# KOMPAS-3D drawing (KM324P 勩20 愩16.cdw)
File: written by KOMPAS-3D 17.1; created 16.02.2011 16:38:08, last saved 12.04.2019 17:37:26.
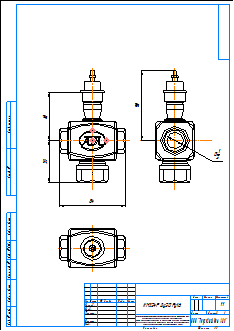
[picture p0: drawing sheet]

Title block, sheet 1: name: KM324P Ду20 Ру16; material: Внимание! Данный продукт является объектом авторского права ООО «Торговый Дом АДЛ». / Запрещается изменение, копирование, распространение / (в том числе путем копирования на другие сайты и ресурсы в Интернете) / или любое иное использование информации и объектов без предварительного / согласия правообладателя (ООО «Торговый Дом АДЛ»).; scale: 1:1; sheets: 1; organisation: ООО "Торговый дом АДЛ"; sheet format: A3; stored path: \\adlc.lan\data\АДЛ_ПКД\3D-модели\ADL production\Клапаны ГРАНРЕГ\Трёхходовой клапан KM324P\KOMPAS 2D\KM324P Ду20 Ру16.cdw

Views: Спереди 1, Проекционный вид 2, Проекционный вид 3
Dimensions and other numbers on the sheet: 84; 53; 61; 90; 1:1; 1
